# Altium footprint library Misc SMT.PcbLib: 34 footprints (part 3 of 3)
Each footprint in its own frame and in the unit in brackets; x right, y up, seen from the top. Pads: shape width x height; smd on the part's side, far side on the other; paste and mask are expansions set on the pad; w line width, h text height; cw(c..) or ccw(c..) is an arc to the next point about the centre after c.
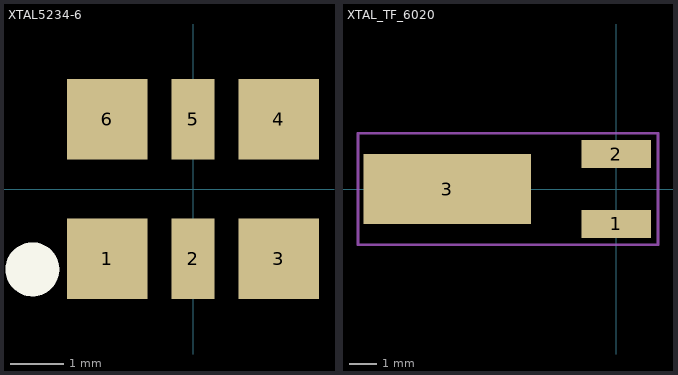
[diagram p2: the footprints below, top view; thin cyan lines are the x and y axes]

## XTAL5234-6 [mm]
pads (6):
  rect 1.5x1.5 smd: 1(-1.6,-1.3) 3(1.6,-1.3) 4(1.6,1.3) 6(-1.6,1.3)
  rect 0.8x1.5 smd: 2(0,-1.3) 5(0,1.3)
Top Overlay:
  circle w0.508: c-3,-1.5 r0.25
3D body: height 1.4, standoff 0, extent -2.575,-1.675 2.575,1.675

## XTAL_TF_6020 [mm] "Tuning fork crystal, 6mm x 2mm"
height 2
pads (3):
  rect 2.5x1 smd: 1(0,-1.25) 2(0,1.25)
  rect 6x2.5 smd: 3(-6.05,0)
Mechanical 15:
  lines w0.1: -9.25,-2 1.5,-2 1.5,2 -9.25,2 -9.25,-2
3D body: height 2, standoff 0, extent -9.008,-1.002 -3.008,0.99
